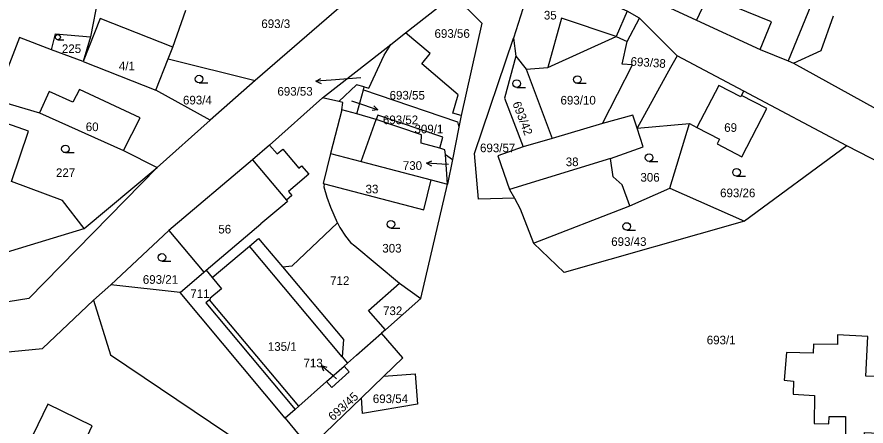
# Model space of a CAD drawing. Extents: x -747333 to -743907, y -1134120 to -1130051.
# Drawn here: x -746528 to -746360.5, y -1132118.9 to -1132038.3 of the extents above; entities that cross this region are included whole.
import ezdxf

# ---------------------------------------------------------------- set-up
doc = ezdxf.new("R2010")
doc.units = 0
for name, color, linetype in [('Hranice parcel', 7, 'Continuous'), ('Parcelní čísla', 7, 'Continuous'), ('Pop  PČ popisy', 7, 'Continuous'), ('Vnitřní kresba', 7, 'Continuous'), ('Značky kultur', 7, 'Continuous')]:
    doc.layers.add(name, color=color, linetype=linetype)

msp = doc.modelspace()

# ---------------------------------------------------------------- linework, layer by layer
at = {"layer": 'Hranice parcel'}
for p, q in [((-746510.62, -1132027.7), (-746513.48, -1132042.23)), ((-746460.24, -1132032.84), (-746481.01, -1132050.82)), ((-746401.77, -1132035.28), (-746393.96, -1132038.89)), ((-746407.66, -1132043.13), (-746405.2, -1132038.56)), ((-746397.81, -1132045.97), (-746405.2, -1132038.56)), ((-746393.96, -1132038.89), (-746381.4, -1132044.7)), ((-746454.25, -1132043.7), (-746451.35, -1132041.44)), ((-746513.48, -1132042.23), (-746514.9, -1132047.08)), ((-746430.06, -1132042.48), (-746429.6, -1132046.01)), ((-746514.9, -1132047.08), (-746521.13, -1132044.79)), ((-746500.6, -1132052.72), (-746498.18, -1132046.57)), ((-746498.18, -1132046.57), (-746481.01, -1132050.82)), ((-746429.6, -1132046.01), (-746427.59, -1132048.57)), ((-746384.64, -1132052.93), (-746397.81, -1132045.97)), ((-746514.9, -1132047.08), (-746500.6, -1132052.72)), ((-746427.59, -1132048.57), (-746422.45, -1132062.24)), ((-746374.84, -1132047.38), (-746324.12, -1132075.54)), ((-746481.01, -1132050.82), (-746489.9, -1132058.63)), ((-746489.9, -1132058.63), (-746500.6, -1132052.72)), ((-746460.97, -1132057.37), (-746459.66, -1132052.67)), ((-746459.66, -1132052.67), (-746459.5, -1132052.08)), ((-746459.66, -1132052.67), (-746456.74, -1132053.65)), ((-746385.07, -1132053.77), (-746384.64, -1132052.93)), ((-746364.32, -1132063.67), (-746384.64, -1132052.93)), ((-746467.74, -1132054.2), (-746478.14, -1132063.56)), ((-746464.53, -1132054.98), (-746467.74, -1132054.2)), ((-746460.97, -1132057.37), (-746463.9, -1132056.59)), ((-746440.38, -1132057.72), (-746440.83, -1132060.01)), ((-746500.33, -1132067.94), (-746489.9, -1132058.63)), ((-746440.83, -1132060.01), (-746442.1, -1132066.42)), ((-746412.54, -1132059.26), (-746422.45, -1132062.24)), ((-746405.65, -1132060.22), (-746395.38, -1132059.32)), ((-746399.22, -1132072.05), (-746395.38, -1132059.32)), ((-746422.45, -1132062.24), (-746428.14, -1132063.91)), ((-746364.32, -1132063.67), (-746384.5, -1132078.54)), ((-746443.05, -1132071.26), (-746443.5, -1132065.38)), ((-746443.5, -1132065.38), (-746442.1, -1132066.42)), ((-746442.1, -1132066.42), (-746443.05, -1132071.26)), ((-746514.69, -1132079.97), (-746500.33, -1132067.94)), ((-746467.37, -1132071.81), (-746467.33, -1132071.18)), ((-746448.34, -1132093.81), (-746443.05, -1132071.26)), ((-746446.32, -1132070.4), (-746443.05, -1132071.26)), ((-746407.1, -1132075.5), (-746399.22, -1132072.05)), ((-746399.22, -1132072.05), (-746384.5, -1132078.54)), ((-746426.1, -1132082.89), (-746407.1, -1132075.5)), ((-746509.43, -1132091.08), (-746498.03, -1132080.35)), ((-746498.03, -1132080.35), (-746491.11, -1132088.59)), ((-746461.32, -1132083.39), (-746452.55, -1132090.79)), ((-746495.78, -1132092.58), (-746491.11, -1132088.59)), ((-746512.89, -1132094.09), (-746509.43, -1132091.08)), ((-746495.78, -1132092.58), (-746509.43, -1132091.08)), ((-746452.55, -1132090.79), (-746448.34, -1132093.81)), ((-746475.1, -1132117.39), (-746495.78, -1132092.58)), ((-746448.34, -1132093.81), (-746455.29, -1132099.94)), ((-746455.29, -1132099.94), (-746456.1, -1132100.64)), ((-746466.92, -1132110.18), (-746463.47, -1132107.14)), ((-746463.47, -1132107.14), (-746462.8, -1132106.55)), ((-746460.04, -1132113.37), (-746455.62, -1132109.09)), ((-746473.11, -1132115.64), (-746475.1, -1132117.39))]:
    msp.add_line(p, q, dxfattribs=at)
for points in [[(-746426.8, -1132029.03), (-746429.42, -1132034.4), (-746427.78, -1132035.27), (-746430.06, -1132042.48)], [(-746405.2, -1132038.56), (-746407.63, -1132037.16), (-746425.03, -1132029.66), (-746426.8, -1132029.03)], [(-746451.35, -1132041.44), (-746442.97, -1132034.81), (-746441.94, -1132033.89)], [(-746441.94, -1132033.89), (-746436.31, -1132039.52), (-746440.38, -1132057.72)], [(-746498.18, -1132046.57), (-746497.26, -1132044.25), (-746494.65, -1132036.93)], [(-746374.84, -1132047.38), (-746369.36, -1132044.89), (-746366.94, -1132038.04)], [(-746521.13, -1132044.79), (-746520.36, -1132041.62), (-746513.48, -1132042.23)], [(-746440.38, -1132057.72), (-746442.05, -1132057.27), (-746440.99, -1132053.65), (-746448.13, -1132047.51), (-746446.52, -1132045.51), (-746451.35, -1132041.44)], [(-746521.13, -1132044.79), (-746527.47, -1132042.31), (-746532.26, -1132054.61)], [(-746429.86, -1132074.04), (-746436.96, -1132074.19), (-746437.77, -1132065.23), (-746430.06, -1132042.48)], [(-746427.59, -1132048.57), (-746423.29, -1132048.22), (-746409.79, -1132042.16), (-746407.66, -1132043.13)], [(-746412.54, -1132059.26), (-746406.61, -1132047.75), (-746408.61, -1132047.62), (-746407.66, -1132043.13)], [(-746467.74, -1132054.2), (-746455.77, -1132044.89), (-746454.25, -1132043.7)], [(-746459.5, -1132052.08), (-746458.58, -1132052.35), (-746455.58, -1132045.82), (-746454.25, -1132043.7)], [(-746381.4, -1132044.7), (-746375.91, -1132046.94), (-746374.84, -1132047.38)], [(-746429.6, -1132046.01), (-746431.83, -1132054.3), (-746428.14, -1132063.91)], [(-746397.81, -1132045.97), (-746399.07, -1132048.25), (-746405.65, -1132060.22)], [(-746459.5, -1132052.08), (-746461.03, -1132051.69), (-746464.53, -1132054.98)], [(-746532.26, -1132054.61), (-746523.53, -1132057.16), (-746506.99, -1132064.63), (-746500.33, -1132067.94)], [(-746463.9, -1132056.59), (-746463.68, -1132055.15), (-746464.53, -1132054.98)], [(-746456.74, -1132053.65), (-746441.09, -1132058.99), (-746440.83, -1132060.01)], [(-746395.38, -1132059.32), (-746393.88, -1132060.1), (-746389.45, -1132062.38), (-746389.91, -1132063.27), (-746385.05, -1132065.88), (-746380.12, -1132056.33), (-746385.07, -1132053.77)], [(-746463.9, -1132056.59), (-746466.16, -1132065.2), (-746467.62, -1132071.1), (-746467.33, -1132071.18)], [(-746514.69, -1132079.97), (-746518.97, -1132074.45), (-746529.02, -1132070.74), (-746525.69, -1132060.77), (-746531.05, -1132058.91), (-746532.75, -1132063.63), (-746550.3, -1132057.95), (-746551.82, -1132062.16), (-746554.68, -1132061.31), (-746558.47, -1132072.6), (-746564.02, -1132080.55)], [(-746443.5, -1132065.38), (-746443.57, -1132064.45), (-746444.59, -1132064.16), (-746448.25, -1132063.14), (-746448.17, -1132061.53), (-746457.15, -1132058.5), (-746460.97, -1132057.37)], [(-746405.65, -1132060.22), (-746406.55, -1132057.63), (-746412.54, -1132059.26)], [(-746407.1, -1132075.5), (-746408.64, -1132071.36), (-746410.41, -1132069.82), (-746410.94, -1132066.21), (-746404.49, -1132063.91), (-746405.65, -1132060.22)], [(-746478.14, -1132063.56), (-746481.55, -1132066.44), (-746498.03, -1132080.35)], [(-746428.14, -1132063.91), (-746433.13, -1132065.67), (-746430.83, -1132072.28), (-746429.86, -1132074.04)], [(-746281.98, -1132106.18), (-746317.29, -1132087.85), (-746364.32, -1132063.67)], [(-746500.33, -1132067.94), (-746525.66, -1132093.79), (-746540.32, -1132096.18), (-746561.68, -1132093.18), (-746580.81, -1132095.03), (-746587.06, -1132096.88), (-746617.06, -1132126.14)], [(-746464.74, -1132078.87), (-746466.1, -1132075.88), (-746466.83, -1132073.88), (-746467.37, -1132071.81)], [(-746467.33, -1132071.18), (-746447.75, -1132076.29), (-746446.32, -1132070.4)], [(-746429.86, -1132074.04), (-746428.72, -1132076.1), (-746426.1, -1132082.89)], [(-746384.5, -1132078.54), (-746420.08, -1132088.64), (-746426.1, -1132082.89)], [(-746564.02, -1132080.55), (-746564.09, -1132087.72), (-746538.22, -1132088.29), (-746538.28, -1132087.14), (-746514.69, -1132079.97)], [(-746475.62, -1132087.56), (-746473.71, -1132087.35), (-746464.74, -1132078.87)], [(-746464.74, -1132078.87), (-746464.33, -1132079.76), (-746463.21, -1132081.52), (-746462.19, -1132082.72), (-746461.32, -1132083.39)], [(-746489.5, -1132089.65), (-746482.1, -1132083.45), (-746480.34, -1132081.97), (-746478.97, -1132083.6), (-746475.62, -1132087.56)], [(-746491.11, -1132088.59), (-746490.68, -1132088.23), (-746489.5, -1132089.65)], [(-746475.62, -1132087.56), (-746463.55, -1132101.86), (-746463.86, -1132105.28), (-746462.8, -1132106.55)], [(-746489.5, -1132089.65), (-746487.65, -1132091.87), (-746489.91, -1132093.76), (-746489.82, -1132093.88), (-746490.01, -1132094.04), (-746490.73, -1132094.66), (-746473.11, -1132115.64)], [(-746455.29, -1132099.94), (-746458.63, -1132096.15), (-746452.55, -1132090.79)], [(-746577.11, -1132104.01), (-746568.02, -1132102.18), (-746541.34, -1132105.39), (-746522.96, -1132103.62), (-746512.89, -1132094.09)], [(-746512.89, -1132094.09), (-746509.52, -1132104.89), (-746463.45, -1132135.88), (-746458.58, -1132138.82), (-746441.38, -1132147.52)], [(-746462.8, -1132106.55), (-746461.02, -1132104.98), (-746456.1, -1132100.64)], [(-746455.62, -1132109.09), (-746451.86, -1132105.45), (-746456.1, -1132100.64)], [(-746355.58, -1132109.28), (-746360.59, -1132109.08), (-746360.16, -1132101.31), (-746366.14, -1132100.93), (-746366.2, -1132102.85), (-746370.91, -1132102.78), (-746370.97, -1132104.58), (-746376.22, -1132104.42), (-746376.7, -1132109.89), (-746374.83, -1132110.1), (-746374.9, -1132112.66), (-746370.69, -1132112.9), (-746370.75, -1132118.4), (-746367.87, -1132118.47), (-746367.81, -1132117.06), (-746364.58, -1132117.06), (-746364.61, -1132121.16), (-746360.9, -1132121.16), (-746360.86, -1132120.23), (-746355.36, -1132120.45)], [(-746463.47, -1132107.14), (-746462.48, -1132108.27), (-746465.9, -1132111.34), (-746466.92, -1132110.18)], [(-746455.62, -1132109.09), (-746449.46, -1132108.64), (-746448.96, -1132114.63), (-746459.82, -1132116.44), (-746460.04, -1132113.37)], [(-746473.11, -1132115.64), (-746472.4, -1132115.01), (-746466.92, -1132110.18)], [(-746475.1, -1132117.39), (-746470.12, -1132123.36), (-746469.01, -1132122.04), (-746460.04, -1132113.37)], [(-746515.99, -1132124.9), (-746513.12, -1132118.91), (-746521.86, -1132114.62), (-746524.85, -1132120.71), (-746522.77, -1132121.69), (-746523.8, -1132123.84)]]:
    msp.add_lwpolyline(points, dxfattribs=at)
at = {"layer": 'Pop  PČ popisy'}
for p, q in [((-746469.004, -1132050.959), (-746468.04, -1132050.39)), ((-746466.01, -1132050.75), (-746469.004, -1132050.959)), ((-746469.004, -1132050.959), (-746467.97, -1132051.389)), ((-746460.15, -1132050.32), (-746466.01, -1132050.75)), ((-746462.03, -1132054.83), (-746459.65, -1132055.63)), ((-746459.65, -1132055.63), (-746456.813, -1132056.607)), ((-746456.813, -1132056.607), (-746457.922, -1132056.754)), ((-746456.813, -1132056.607), (-746457.596, -1132055.808)), ((-746447.184, -1132067.091), (-746446.15, -1132066.661)), ((-746444.19, -1132067.3), (-746447.184, -1132067.091)), ((-746447.184, -1132067.091), (-746446.22, -1132067.66)), ((-746442.88, -1132067.4), (-746444.19, -1132067.3)), ((-746465.7, -1132108.98), (-746467.965, -1132107.011)), ((-746467.965, -1132107.011), (-746466.881, -1132107.29)), ((-746467.965, -1132107.011), (-746467.538, -1132108.046)), ((-746464.95, -1132109.64), (-746465.7, -1132108.98))]:
    msp.add_line(p, q, dxfattribs=at)
at = {"layer": 'Vnitřní kresba'}
for p, q in [((-746391.76, -1132034.12), (-746393.96, -1132038.89)), ((-746379.18, -1132039.26), (-746391.76, -1132034.12)), ((-746371.46, -1132036.05), (-746375.91, -1132046.94)), ((-746407.63, -1132037.16), (-746409.79, -1132042.16)), ((-746511.56, -1132038.61), (-746514.9, -1132047.08)), ((-746497.26, -1132044.25), (-746511.56, -1132038.61)), ((-746420.61, -1132038.55), (-746423.29, -1132048.22)), ((-746409.79, -1132042.16), (-746420.61, -1132038.55)), ((-746381.4, -1132044.7), (-746379.18, -1132039.26)), ((-746389.59, -1132051.78), (-746393.88, -1132060.1)), ((-746385.21, -1132054.04), (-746389.59, -1132051.78)), ((-746521.59, -1132052.98), (-746523.53, -1132057.16)), ((-746516.95, -1132055.07), (-746521.59, -1132052.98)), ((-746515.64, -1132052.6), (-746516.95, -1132055.07)), ((-746503.66, -1132058.16), (-746515.64, -1132052.6)), ((-746385.07, -1132053.77), (-746385.21, -1132054.04)), ((-746506.99, -1132064.63), (-746503.66, -1132058.16)), ((-746460.07, -1132066.8), (-746457.15, -1132058.5)), ((-746456.82, -1132057.68), (-746457.15, -1132058.5)), ((-746443.98, -1132062.01), (-746456.82, -1132057.68)), ((-746478.14, -1132063.56), (-746476.64, -1132065.26)), ((-746444.59, -1132064.16), (-746443.98, -1132062.01)), ((-746476.64, -1132065.26), (-746475.57, -1132064.36)), ((-746475.57, -1132064.36), (-746472.39, -1132068.12)), ((-746466.16, -1132065.2), (-746460.07, -1132066.8)), ((-746481.55, -1132066.44), (-746474.84, -1132074.39)), ((-746460.07, -1132066.8), (-746446.32, -1132070.4)), ((-746410.94, -1132066.21), (-746430.83, -1132072.28)), ((-746472.39, -1132068.12), (-746471.83, -1132067.66)), ((-746471.83, -1132067.66), (-746470.44, -1132069.31)), ((-746470.44, -1132069.31), (-746473.14, -1132071.58)), ((-746473.14, -1132071.58), (-746474.43, -1132072.67)), ((-746473.75, -1132073.47), (-746474.84, -1132074.39)), ((-746474.43, -1132072.67), (-746473.75, -1132073.47)), ((-746475.14, -1132075.1), (-746479.87, -1132079.1)), ((-746474.61, -1132074.66), (-746475.14, -1132075.1)), ((-746474.84, -1132074.39), (-746474.61, -1132074.66)), ((-746490.68, -1132088.23), (-746479.87, -1132079.1)), ((-746463.86, -1132105.28), (-746482.1, -1132083.45)), ((-746472.4, -1132115.01), (-746490.01, -1132094.04))]:
    msp.add_line(p, q, dxfattribs=at)
at = {"layer": 'Značky kultur'}
for p, q in [((-746519.895, -1132042.78), (-746518.723, -1132042.78)), ((-746492.053, -1132051.28), (-746490.303, -1132051.28)), ((-746417.463, -1132051.37), (-746415.713, -1132051.37)), ((-746429.433, -1132052.18), (-746427.683, -1132052.18)), ((-746518.413, -1132065.04), (-746516.663, -1132065.04)), ((-746403.323, -1132066.75), (-746401.573, -1132066.75)), ((-746386.073, -1132069.67), (-746384.323, -1132069.67)), ((-746454.233, -1132079.89), (-746452.483, -1132079.89)), ((-746407.733, -1132080.34), (-746405.983, -1132080.34)), ((-746499.383, -1132086.43), (-746497.633, -1132086.43))]:
    msp.add_line(p, q, dxfattribs=at)
for centre, radius in [((-746519.895, -1132042.277), 0.502), ((-746492.053, -1132050.53), 0.75), ((-746417.463, -1132050.62), 0.75), ((-746429.433, -1132051.43), 0.75), ((-746518.413, -1132064.29), 0.75), ((-746403.323, -1132066), 0.75), ((-746386.073, -1132068.92), 0.75), ((-746454.233, -1132079.14), 0.75), ((-746407.733, -1132079.59), 0.75), ((-746499.383, -1132085.68), 0.75)]:
    msp.add_circle(centre, radius, dxfattribs=at)

# ---------------------------------------------------------------- texts
at = {"layer": 'Parcelní čísla'}
for s, p in [('35', (-746424.07, -1132038.79)), ('693/3', (-746479.78, -1132040.473)), ('693/56', (-746445.63, -1132042.4)), ('225', (-746519.11, -1132045.4)), ('4/1', (-746507.87, -1132048.81)), ('693/53', (-746476.611, -1132053.803)), ('693/55', (-746454.49, -1132054.57)), ('693/4', (-746495.23, -1132055.53)), ('693/10', (-746420.79, -1132055.55)), ('693/52', (-746455.81, -1132059.423)), ('60', (-746514.4, -1132060.79)), ('309/1', (-746449.583, -1132061.22)), ('69', (-746388.51, -1132060.94)), ('693/57', (-746436.66, -1132064.95)), ('730', (-746451.879, -1132068.426)), ('38', (-746419.76, -1132067.7)), ('227', (-746520.28, -1132069.84)), ('306', (-746405.03, -1132070.75)), ('33', (-746459.23, -1132073.06)), ('693/26', (-746389.32, -1132073.82)), ('56', (-746488.26, -1132080.97)), ('693/43', (-746410.79, -1132083.42)), ('303', (-746455.93, -1132084.73)), ('693/21', (-746503.15, -1132090.89)), ('712', (-746466.214, -1132091.11)), ('711', (-746493.784, -1132093.69)), ('732', (-746455.784, -1132097.06)), ('693/1', (-746391.95, -1132102.82)), ('135/1', (-746478.5, -1132104.1)), ('713', (-746471.464, -1132107.35)), ('693/54', (-746457.8, -1132114.4))]:
    msp.add_text(s, height=1.7, dxfattribs=at).set_placement(p)
for s, rotation, p in [('693/38', 356, (-746407.029, -1132047.867)), ('693/42', 291, (-746430.303, -1132055.324)), ('693/45', 42, (-746465.651, -1132118.001))]:
    msp.add_text(s, height=1.7, rotation=rotation, dxfattribs=at).set_placement(p)

doc.saveas('drawing.dxf')
